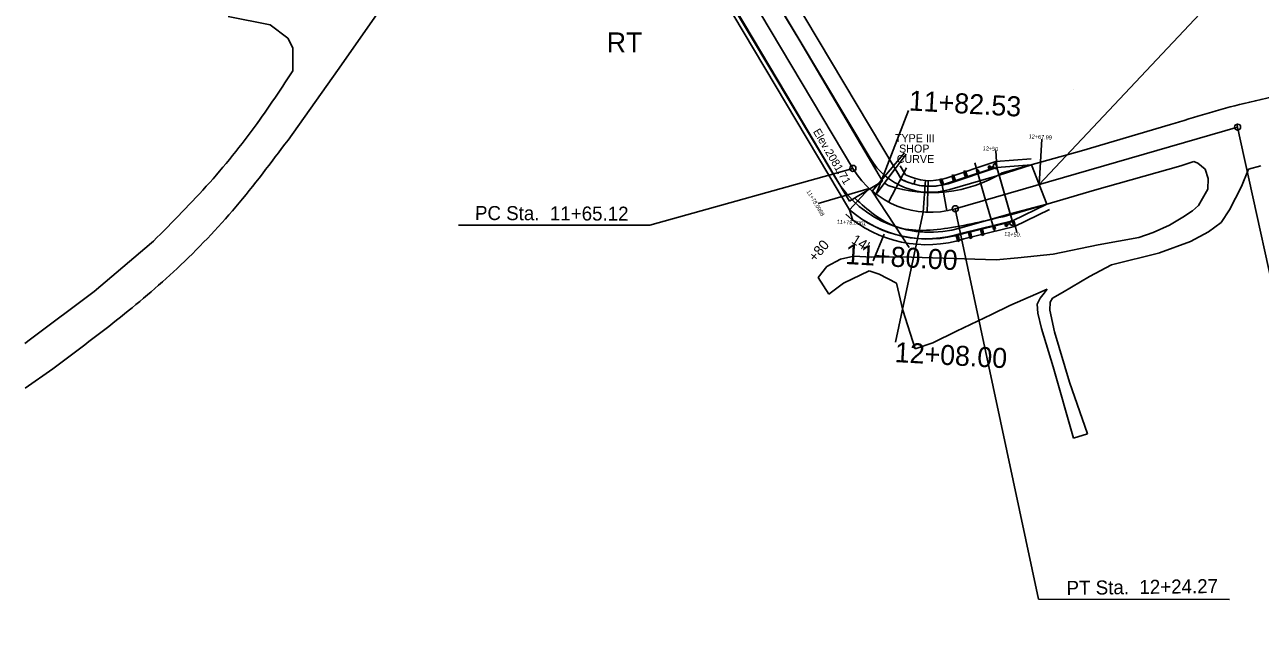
# Model space of a CAD drawing. Extents: x 757145 to 758829, y 592169 to 594973.
# Drawn here: x 757319 to 757937, y 594355 to 594652 of the extents above; entities that cross this region are included whole.
import ezdxf

# ---------------------------------------------------------------- set-up
doc = ezdxf.new("R2010")
doc.units = 0
for name, color, linetype in [('COGO Default Point Elevation', 7, 'Continuous'), ('Default', 7, 'Continuous'), ('Old_Level_25', 7, 'Continuous'), ('Prop Dimension', 7, 'Continuous'), ('Prop Guardrail Anchor Unit CELL', 7, 'Continuous'), ('Prop Horizontal Alignment Direction Label', 7, 'Continuous'), ('Prop Horizontal Alignment Tick Small', 7, 'Continuous'), ('Prop Paved Shoulder', 7, 'Continuous'), ('Prop Roadway Bridge', 7, 'Continuous'), ('Prop Structure Anchor Unit CELL', 7, 'Continuous'), ('Prop Superelevation  Arrow CELL', 7, 'Continuous'), ('Scratch_Level_4', 7, 'Continuous')]:
    doc.layers.add(name, color=color, linetype=linetype)

msp = doc.modelspace()

# ---------------------------------------------------------------- linework, layer by layer
at = {"layer": 'COGO Default Point Elevation'}
for p, q in [((757758.95, 594588.42), (757742.81, 594569.33)), ((757744.78, 594567.75), (757759.83, 594587.72)), ((757760.03, 594580.93), (757751.09, 594563.77)), ((757801.8, 594580.24), (757778.08, 594572.35)), ((757788.51, 594579.02), (757789.46, 594579.33)), ((757789.47, 594576.14), (757788.51, 594579.02)), ((757789.94, 594577.89), (757788.51, 594579.02)), ((757789.46, 594579.33), (757788.99, 594577.58)), ((757790.41, 594576.45), (757789.46, 594579.33)), ((757794.09, 594583.47), (757799.49, 594564.83)), ((757794.92, 594579.55), (757795.87, 594579.86)), ((757795.4, 594578.11), (757794.92, 594579.55)), ((757794.92, 594579.55), (757796.35, 594578.42)), ((757795.4, 594578.11), (757795.87, 594579.86)), ((757796.35, 594578.42), (757795.87, 594579.86)), ((757800.85, 594581.52), (757801.8, 594581.83)), ((757801.33, 594580.08), (757800.85, 594581.52)), ((757800.85, 594581.52), (757802.28, 594580.39)), ((757801.33, 594580.08), (757801.8, 594581.83)), ((757801.33, 594580.08), (757802.28, 594580.39)), ((757802.28, 594580.39), (757801.8, 594581.83)), ((757803.44, 594581.55), (757802.05, 594581.09)), ((757802.27, 594580.4), (757803.67, 594580.87)), ((757804.13, 594583.21), (757803.28, 594582.03)), ((757803.28, 594582.03), (757803.67, 594580.87)), ((757803.67, 594580.87), (757805.06, 594580.43)), ((757804.13, 594583.21), (757804.42, 594583.31)), ((757805.35, 594580.52), (757804.42, 594583.31)), ((757804.65, 594582.98), (757813.54, 594552.24)), ((757805.06, 594580.43), (757805.35, 594580.52)), ((757764.27, 594574.85), (757763.82, 594573.16)), ((757768.28, 594558.83), (757769.55, 594574.78)), ((757770.84, 594574.7), (757770.27, 594558.72)), ((757776.65, 594575.08), (757777.59, 594575.39)), ((757777.6, 594572.2), (757776.65, 594575.08)), ((757778.07, 594573.95), (757776.65, 594575.08)), ((757777.59, 594575.39), (757777.12, 594573.64)), ((757777.12, 594573.64), (757778.07, 594573.95)), ((757777.12, 594573.64), (757778.55, 594572.51)), ((757780.22, 594559.47), (757777.25, 594575.19)), ((757778.55, 594572.51), (757777.59, 594575.39)), ((757777.6, 594572.2), (757778.07, 594573.95)), ((757777.6, 594572.2), (757778.55, 594572.51)), ((757782.58, 594577.05), (757783.53, 594577.36)), ((757783.53, 594574.17), (757782.58, 594577.05)), ((757784.01, 594575.92), (757782.58, 594577.05)), ((757783.53, 594577.36), (757783.06, 594575.61)), ((757783.06, 594575.61), (757784.01, 594575.92)), ((757783.06, 594575.61), (757784.48, 594574.48)), ((757784.48, 594574.48), (757783.53, 594577.36)), ((757783.53, 594574.17), (757784.01, 594575.92)), ((757783.53, 594574.17), (757784.48, 594574.48)), ((757788.99, 594577.58), (757789.94, 594577.89)), ((757788.99, 594577.58), (757790.41, 594576.45)), ((757789.47, 594576.14), (757789.94, 594577.89)), ((757789.47, 594576.14), (757790.41, 594576.45)), ((757795.4, 594578.11), (757796.35, 594578.42)), ((757803.93, 594549.46), (757799.49, 594564.83)), ((757811.54, 594553.69), (757812.48, 594554.81)), ((757812.48, 594554.81), (757812.78, 594554.88)), ((757812.78, 594554.88), (757813.48, 594552.03)), ((757809.63, 594553.23), (757785.36, 594547.23)), ((757790.94, 594548.61), (757791.91, 594548.85)), ((757790.94, 594548.61), (757791.67, 594545.66)), ((757790.94, 594548.61), (757792.28, 594547.38)), ((757791.31, 594547.13), (757791.91, 594548.85)), ((757791.91, 594548.85), (757792.64, 594545.9)), ((757797.01, 594550.11), (757797.98, 594550.35)), ((757797.01, 594550.11), (757797.74, 594547.16)), ((757797.01, 594550.11), (757798.34, 594548.88)), ((757797.37, 594548.64), (757797.98, 594550.35)), ((757797.37, 594548.64), (757798.34, 594548.88)), ((757798.71, 594547.4), (757797.37, 594548.64)), ((757798.34, 594548.88), (757797.74, 594547.16)), ((757797.98, 594550.35), (757798.71, 594547.4)), ((757803.07, 594551.61), (757804.05, 594551.85)), ((757803.07, 594551.61), (757803.44, 594550.14)), ((757803.07, 594551.61), (757804.41, 594550.38)), ((757803.44, 594550.14), (757804.05, 594551.85)), ((757803.44, 594550.14), (757804.41, 594550.38)), ((757804.05, 594551.85), (757804.41, 594550.38)), ((757809.14, 594553.11), (757810.11, 594553.35)), ((757809.14, 594553.11), (757809.51, 594551.64)), ((757809.14, 594553.11), (757810.48, 594551.88)), ((757809.51, 594551.64), (757810.11, 594553.35)), ((757809.51, 594551.64), (757810.48, 594551.88)), ((757810.11, 594553.35), (757810.48, 594551.88)), ((757810.12, 594553.34), (757811.54, 594553.69)), ((757811.72, 594553), (757810.29, 594552.64)), ((757811.84, 594552.51), (757811.54, 594553.69)), ((757813.18, 594551.96), (757811.84, 594552.51)), ((757813.18, 594551.96), (757813.48, 594552.03)), ((757784.87, 594547.11), (757785.84, 594547.35)), ((757784.87, 594547.11), (757785.6, 594544.16)), ((757784.87, 594547.11), (757786.21, 594545.87)), ((757785.24, 594545.63), (757785.84, 594547.35)), ((757785.24, 594545.63), (757786.21, 594545.87)), ((757786.57, 594544.4), (757785.24, 594545.63)), ((757786.21, 594545.87), (757785.6, 594544.16)), ((757785.6, 594544.16), (757786.57, 594544.4)), ((757785.84, 594547.35), (757786.57, 594544.4)), ((757791.31, 594547.13), (757792.28, 594547.38)), ((757792.64, 594545.9), (757791.31, 594547.13)), ((757792.28, 594547.38), (757791.67, 594545.66)), ((757791.67, 594545.66), (757792.64, 594545.9)), ((757797.74, 594547.16), (757798.71, 594547.4))]:
    msp.add_line(p, q, dxfattribs=at)
for points in [[(757827.67, 594595.29), (757826.37, 594572.61)], [(757804.58, 594589.5), (757805.17, 594581.05)], [(757715.93, 594563.01), (757741.38, 594570.59)], [(757733.21, 594554.55), (757731.58, 594559.96)], [(757815.23, 594548.53), (757813.8, 594554.24)]]:
    msp.add_lwpolyline(points, dxfattribs=at)
at = {"layer": 'Default'}
for p, q in [((757674.88, 594697.27), (757706.73, 594644.4)), ((757700.05, 594617.37), (757658.35, 594687.7)), ((757442.04, 594652.32), (757421.04, 594656.49)), ((757450.78, 594645.66), (757442.04, 594652.32)), ((757453.25, 594640.85), (757450.78, 594645.66)), ((757453.36, 594636.45), (757453.25, 594640.85)), ((757706.73, 594644.4), (757748.03, 594574.22)), ((757453.34, 594629.46), (757453.36, 594636.45)), ((757731.47, 594564.29), (757700.05, 594617.37)), ((757903.65, 594584.09), (757897.12, 594581.94)), ((757905.63, 594583.19), (757903.65, 594584.09)), ((757909.35, 594580.24), (757905.63, 594583.19)), ((757910.8, 594575.6), (757909.35, 594580.24)), ((757930.93, 594580.27), (757927.5, 594571.65)), ((757937.03, 594581.88), (757930.93, 594580.27)), ((757731.47, 594564.29), (757748.03, 594574.22)), ((757910.54, 594570.25), (757910.8, 594575.6)), ((757905.86, 594562.15), (757910.54, 594570.25)), ((757927.5, 594571.65), (757921.47, 594559.95)), ((757902.86, 594559.46), (757905.86, 594562.15)), ((757921.47, 594559.95), (757917.31, 594553.59)), ((757891.4, 594552.34), (757898.15, 594556.27)), ((757898.15, 594556.27), (757902.86, 594559.46)), ((757876.2, 594546.02), (757883.36, 594548.57)), ((757883.36, 594548.57), (757891.4, 594552.34)), ((757911.02, 594548.95), (757901.93, 594544.15)), ((757917.31, 594553.59), (757911.02, 594548.95)), ((757353.95, 594519.05), (757382.68, 594543.42)), ((757382.68, 594543.42), (757383.61, 594544.21)), ((757833.32, 594537.8), (757855.77, 594542.41)), ((757855.77, 594542.41), (757876.2, 594546.02)), ((757901.93, 594544.15), (757886.49, 594538.48)), ((757726.95, 594535.21), (757733.76, 594536.77)), ((757733.76, 594536.77), (757742.63, 594536.3)), ((757804.85, 594534.9), (757815.64, 594535.97)), ((757815.64, 594535.97), (757833.32, 594537.8)), ((757886.54, 594538.42), (757862.44, 594532.44)), ((757886.49, 594538.48), (757886.54, 594538.42)), ((757715.79, 594526.11), (757720.14, 594531.53)), ((757720.14, 594531.53), (757726.95, 594535.21)), ((757741.34, 594529.45), (757728.57, 594523.33)), ((757741.37, 594529.38), (757741.38, 594529.51)), ((757746.35, 594527.78), (757741.37, 594529.38)), ((757862.44, 594532.44), (757851.49, 594526.55)), ((757721.19, 594517.73), (757715.79, 594526.11)), ((757728.57, 594523.33), (757721.19, 594517.73)), ((757754.93, 594523.2), (757746.35, 594527.78)), ((757758.16, 594509.72), (757754.93, 594523.2)), ((757851.49, 594526.55), (757837.98, 594518.63)), ((757353.95, 594519.05), (757322.24, 594495.27)), ((757824.63, 594517.75), (757811.69, 594512.12)), ((757830.28, 594520.3), (757824.63, 594517.75)), ((757826.74, 594515.79), (757828.81, 594518.26)), ((757828.81, 594518.26), (757830.28, 594520.3)), ((757837.98, 594518.63), (757833.04, 594515.83)), ((757811.69, 594512.12), (757802.54, 594507.54)), ((757825.39, 594512.69), (757826.74, 594515.79)), ((757825.6, 594508.25), (757825.39, 594512.69)), ((757831.81, 594513.79), (757831.65, 594509.75)), ((757833.04, 594515.83), (757831.81, 594513.79)), ((757764.36, 594490.48), (757758.16, 594509.72)), ((757802.54, 594507.54), (757784.93, 594499.22)), ((757827.48, 594500.55), (757825.6, 594508.25)), ((757831.65, 594509.75), (757833.9, 594498.92)), ((757784.93, 594499.22), (757773.2, 594493.44)), ((757833.31, 594481.41), (757827.48, 594500.55)), ((757833.9, 594498.92), (757841.45, 594473.84)), ((757322.24, 594495.27), (757319.31, 594493.16)), ((757773.2, 594493.44), (757764.36, 594490.48)), ((757333.33, 594480.52), (757319.57, 594470.74)), ((757843.42, 594445.84), (757833.31, 594481.41)), ((757841.45, 594473.84), (757850.52, 594447.97)), ((757843.42, 594445.84), (757850.52, 594447.97))]:
    msp.add_line(p, q, dxfattribs=at)
msp.add_lwpolyline([(757519.93, 594693.54), (757499.75, 594664.06), (757475.67, 594629.54), (757450.9, 594594.8)], dxfattribs=at)
for points in [[(757383.61, 594544.21), (757411.75, 594573.56), (757436.96, 594605.16), (757453.34, 594629.46)], [(757891.94, 594602.51), (757928.7, 594613.12), (757974.81, 594621.08), (758013.38, 594621.87), (758059.79, 594614.97), (758103.42, 594606.71), (758144.86, 594596.26), (758186.7, 594584.49), (758228.79, 594570.5), (758271.22, 594556.18), (758311.98, 594537.66), (758352.07, 594519.49), (758392.24, 594498.74), (758431.47, 594479.21), (758471.03, 594457.32), (758502.93, 594438.31), (758541.94, 594414.39), (758575.01, 594392.91), (758612.38, 594365.9), (758644.48, 594342.28), (758681.18, 594311.67), (758729.99, 594270.62), (758760.77, 594240.66)], [(757450.9, 594594.8), (757424.84, 594561.43), (757395.45, 594530.62), (757365.24, 594504.78), (757333.33, 594480.52)]]:
    msp.add_spline(points, degree=3, dxfattribs=at)
at = {"layer": 'Prop Dimension'}
for p, q in [((757843.63, 594619.96), (757843.63, 594619.96)), ((757754.01, 594580), (757744.78, 594567.75)), ((757757.43, 594575.22), (757754.33, 594580.41)), ((757805.2, 594581.07), (757780.76, 594572.98)), ((757756.39, 594573.99), (757756.39, 594573.99)), ((757758.2, 594574.81), (757757.43, 594575.22)), ((757758.76, 594574.54), (757758.2, 594574.81)), ((757760.52, 594573.77), (757758.76, 594574.54)), ((757762.59, 594573.07), (757760.52, 594573.77)), ((757764.07, 594572.68), (757762.59, 594573.07)), ((757780.76, 594572.98), (757777.39, 594572.19)), ((757746.61, 594570.17), (757744.78, 594567.75)), ((757771.55, 594571.72), (757769.21, 594571.84)), ((757773.87, 594571.78), (757771.55, 594571.72)), ((757777.39, 594572.19), (757773.87, 594571.78)), ((757787.99, 594547.97), (757813.8, 594554.24)), ((757742.72, 594536.19), (757757.17, 594536.43)), ((757757.17, 594536.43), (757804.85, 594534.9))]:
    msp.add_line(p, q, dxfattribs=at)
for points in [[(757760.99, 594609.62), (757744.78, 594567.75)], [(757769.21, 594571.84), (757766.46, 594572.16), (757764.07, 594572.68)], [(757761.4, 594541.08), (757742.81, 594569.33)], [(757754.51, 594493.83), (757768.27, 594558.83)]]:
    msp.add_lwpolyline(points, dxfattribs=at)
msp.add_arc((757770.53, 594604.47), 59.14, 228.8162, 287.17631, dxfattribs=at)
at = {"layer": 'Prop Guardrail Anchor Unit CELL'}
for p, q in [((757675.24, 594697.36), (757741.82, 594585.76)), ((757655.82, 594690.87), (757724.64, 594575.51)), ((757806.31, 594577.21), (757822.56, 594582.46)), ((757822.56, 594582.46), (757830.19, 594562.76)), ((757781.6, 594570.07), (757806.31, 594577.21)), ((757811.87, 594558), (757830.19, 594562.76)), ((757787.16, 594550.85), (757811.87, 594558))]:
    msp.add_line(p, q, dxfattribs=at)
for radius in [35, 55]:
    msp.add_arc((757771.87, 594603.69), radius, 210.81837, 286.13406, dxfattribs=at)
at = {"layer": 'Prop Horizontal Alignment Direction Label'}
for p, q in [((757847.47, 594589.39), (757891.94, 594602.51)), ((757847.47, 594589.39), (757807.82, 594578.36)), ((757897.12, 594581.94), (757853.96, 594569.81)), ((757750.91, 594572.05), (757748.85, 594573.34)), ((757853.96, 594569.81), (757813.83, 594557.92))]:
    msp.add_line(p, q, dxfattribs=at)
msp.add_ellipse((757772.54, 594636.61), major_axis=(48.94, -47.37), ratio=0.999539, start_param=5.157921, end_param=6.025957, dxfattribs=at)
msp.add_spline([(757813.83, 594557.92), (757782.49, 594551.08), (757754.63, 594551.61), (757734.19, 594565.7)], degree=3, dxfattribs=at)
at = {"layer": 'Prop Horizontal Alignment Tick Small'}
for p, q in [((757648.63, 594722.44), (757733.23, 594580.63)), ((757784.38, 594560.46), (757925.47, 594601.27))]:
    msp.add_line(p, q, dxfattribs=at)
msp.add_arc((757771.87, 594603.69), 45, 210.81837, 286.13406, dxfattribs=at)
at = {"layer": 'Prop Paved Shoulder'}
for p, q in [((757757.49, 594575.1), (757754.32, 594580.41)), ((757780.77, 594572.95), (757805.17, 594581.05)), ((757805.17, 594581.05), (757822.56, 594582.46)), ((757813.04, 594554.4), (757830.19, 594562.76)), ((757787.9, 594548.27), (757813.04, 594554.4))]:
    msp.add_line(p, q, dxfattribs=at)
for centre, radius, start, end in [((757771.87, 594603.69), 32, 243.28044, 286.13406), ((757770.1, 594604.03), 58.53, 228.84124, 287.70356)]:
    msp.add_arc(centre, radius, start, end, dxfattribs=at)
at = {"layer": 'Prop Roadway Bridge'}
for p, q in [((757826.37, 594572.61), (757948.13, 594702.11)), ((757925.05, 594602.71), (757974.94, 594375.77)), ((757733.23, 594580.63), (757631.67, 594552.2)), ((757784.38, 594560.46), (757826.01, 594365.36)), ((757631.67, 594552.2), (757536.13, 594552.23)), ((757826.01, 594365.36), (757921.44, 594365.19))]:
    msp.add_line(p, q, dxfattribs=at)
for centre in [(757925.47, 594601.27), (757733.23, 594580.63), (757784.38, 594560.46)]:
    msp.add_circle(centre, 1.5, dxfattribs=at)
at = {"layer": 'Prop Structure Anchor Unit CELL'}
for p, q in [((757678.01, 594708.32), (757754.32, 594580.41)), ((757652.18, 594693.08), (757731.58, 594559.96)), ((757731.58, 594559.96), (757741.38, 594570.59)), ((757738.88, 594567.94), (757741.36, 594570.62))]:
    msp.add_line(p, q, dxfattribs=at)
at = {"layer": 'Prop Superelevation  Arrow CELL'}
for p, q in [((757811.87, 594558), (757806.31, 594577.21)), ((757743.28, 594534.35), (757748.8, 594547.73))]:
    msp.add_line(p, q, dxfattribs=at)
at = {"layer": 'Scratch_Level_4'}
for p, q in [((757804.57, 594584.01), (757822.31, 594585.45)), ((757756.9, 594581.94), (757759.58, 594577.46)), ((757779.85, 594575.82), (757804.57, 594584.01)), ((757814.06, 594551.56), (757831.5, 594560.07)), ((757788.71, 594545.38), (757814.06, 594551.56))]:
    msp.add_line(p, q, dxfattribs=at)
for centre, radius, start, end in [((757771.64, 594600.57), 26.08, 242.4408, 288.3505), ((757770.1, 594604.03), 61.53, 228.84124, 287.60459)]:
    msp.add_arc(centre, radius, start, end, dxfattribs=at)

# ---------------------------------------------------------------- texts
at = {"layer": 'COGO Default Point Elevation'}
for s, height, rotation, p in [('TYPE III', 4, 359.89587, (757754.22, 594593.75)), ('12+67.99', 2, 356.78993, (757821.03, 594595.67)), ('SHOP', 4, 359.89587, (757756.31, 594588.54)), ('12+50', 2, 356.78993, (757798.08, 594589.71)), ('CURVE', 4, 359.89587, (757755.12, 594583.35)), ('11+78.0958', 2, 300.81837, (757709.96, 594569.11)), ('11+78.0961', 2, 356.78993, (757725.17, 594553)), ('12+50.', 2, 356.78993, (757808.8, 594546.88))]:
    msp.add_text(s, height=height, rotation=rotation, dxfattribs=at).set_placement(p)
at = {"layer": 'Old_Level_25'}
msp.add_text('Elev.2081.71', height=4, rotation=300.43607, dxfattribs=at).set_placement((757713.15, 594599.06))
at = {"layer": 'Prop Dimension'}
for s, rotation, p in [('RT', 359.9825, (757610.19, 594638.58)), ('11+82.53', 356.78993, (757760.99, 594609.62)), ('11+80.00', 356.78993, (757729.2, 594532.87)), ('12+08.00', 356.78993, (757753.95, 594483.85))]:
    msp.add_text(s, height=10, rotation=rotation, dxfattribs=at).set_placement(p)
at = {"layer": 'Prop Roadway Bridge'}
for s, rotation, p in [('PC Sta.  11+65.12', 359.73133, (757544.32, 594554.85)), ('PT Sta.  12+24.27', 0.76053, (757840.03, 594367.42))]:
    msp.add_text(s, height=7, rotation=rotation, dxfattribs=at).set_placement(p)
at = {"layer": 'Prop Superelevation  Arrow CELL'}
for s, rotation, p in [('+80', 49.76397, (757714.36, 594533.56)), ("14'", 328.67665, (757732.08, 594543.66))]:
    msp.add_text(s, height=5, rotation=rotation, dxfattribs=at).set_placement(p)

doc.saveas('drawing.dxf')
